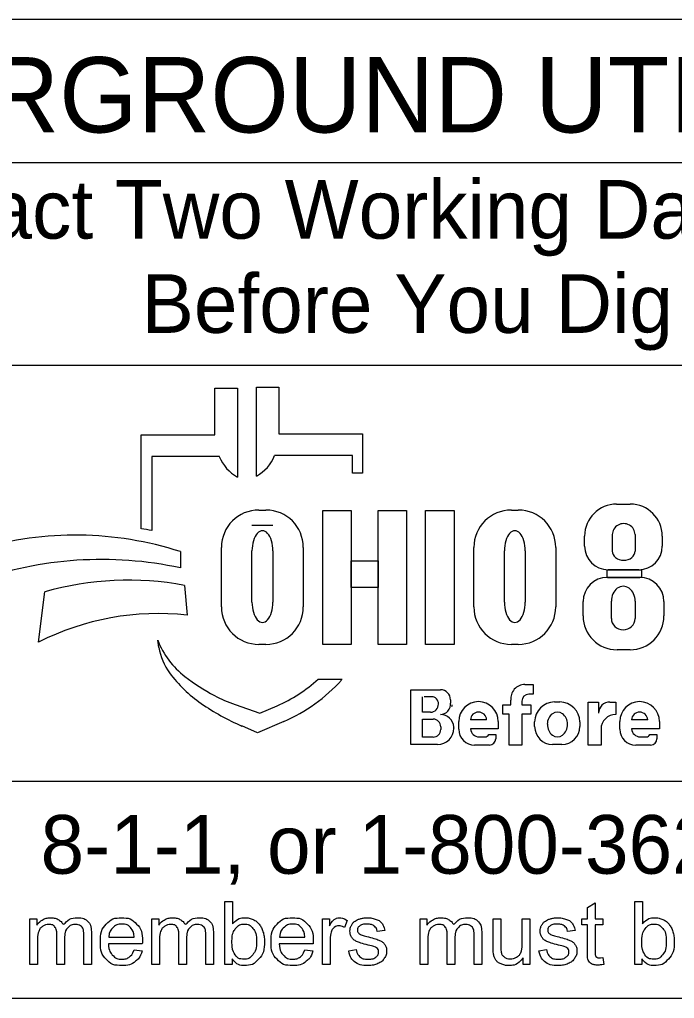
# Model space of a CAD drawing. Extents: x 25.6 to 80.6, y 0.2 to 24.5.
# Drawn here: x 38.78 to 40.344, y 2.373 to 4.711 of the extents above; entities that cross this region are included whole.
import ezdxf

# ---------------------------------------------------------------- set-up
doc = ezdxf.new("R2010")
doc.units = 0
doc.layers.add('SH_Data', color=7, linetype='Continuous')
doc.layers.add('SH_Text', color=7, linetype='Continuous')

msp = doc.modelspace()

# ---------------------------------------------------------------- linework, layer by layer
at = {"layer": 'SH_Data'}
for p, q in [((42.1403, 4.7105), (37.8903, 4.7105)), ((37.8903, 4.369), (42.1403, 4.369)), ((37.8903, 3.8856), (42.1403, 3.8856)), ((42.1403, 2.8909), (37.8903, 2.8909)), ((42.1403, 2.373), (37.8903, 2.373))]:
    msp.add_line(p, q, dxfattribs=at)
at = {"layer": 'SH_Text'}
for p, q in [((39.2463, 3.7186), (39.2463, 3.83)), ((39.2463, 3.83), (39.3, 3.83)), ((39.3, 3.83), (39.3, 3.618)), ((39.3457, 3.6203), (39.3457, 3.8324)), ((39.3457, 3.8324), (39.3993, 3.8324)), ((39.3993, 3.8324), (39.3993, 3.7209)), ((39.0704, 3.4947), (39.0704, 3.7186)), ((39.0704, 3.7186), (39.2463, 3.7186)), ((39.3993, 3.7209), (39.5985, 3.7209)), ((39.5985, 3.7209), (39.5985, 3.6271)), ((39.0956, 3.6671), (39.0956, 3.4903)), ((39.2568, 3.6671), (39.0956, 3.6671)), ((39.5753, 3.6694), (39.3889, 3.6694)), ((39.5753, 3.6271), (39.5753, 3.6694)), ((39.5985, 3.6271), (39.5753, 3.6271)), ((40.2059, 3.5534), (40.2386, 3.5534)), ((39.3513, 3.5394), (39.3679, 3.5394)), ((39.9544, 3.5394), (39.9709, 3.5394)), ((39.3846, 3.5024), (39.3348, 3.5024)), ((40.1296, 3.4528), (40.1296, 3.4771)), ((40.1958, 3.4414), (40.1958, 3.4807)), ((40.2499, 3.4807), (40.2499, 3.4414)), ((40.315, 3.4771), (40.315, 3.4528)), ((39.1637, 3.44), (39.1637, 3.4012)), ((39.2619, 3.3079), (39.2619, 3.4499)), ((39.3348, 3.3193), (39.3348, 3.4416)), ((39.3846, 3.4416), (39.3846, 3.3193)), ((39.4573, 3.4499), (39.4573, 3.3079)), ((39.8649, 3.3079), (39.8649, 3.4499)), ((39.9378, 3.3193), (39.9378, 3.4416)), ((39.9876, 3.4416), (39.9876, 3.3193)), ((40.0604, 3.4499), (40.0604, 3.3079)), ((40.259, 3.3968), (40.1856, 3.3968)), ((40.1838, 3.3785), (40.2611, 3.3785)), ((38.8248, 3.2238), (38.8395, 3.344)), ((39.1736, 3.3594), (39.1799, 3.2884)), ((40.1259, 3.2865), (40.1259, 3.3206)), ((40.1934, 3.2806), (40.1934, 3.3215)), ((40.2502, 3.3215), (40.2502, 3.2806)), ((40.319, 3.3206), (40.319, 3.2865)), ((39.1125, 3.2109), (39.1095, 3.2289)), ((39.3679, 3.2184), (39.3513, 3.2184)), ((39.9709, 3.2184), (39.9544, 3.2184)), ((40.238, 3.2056), (40.2069, 3.2056)), ((39.4928, 3.1351), (39.5503, 3.1351)), ((39.7141, 2.9793), (39.7141, 3.11)), ((39.7141, 3.11), (39.7853, 3.11)), ((39.9867, 3.1228), (40.0062, 3.1228)), ((40.0062, 3.1228), (40.0062, 3.0998)), ((39.7421, 3.0565), (39.7421, 3.0935)), ((39.7673, 3.0935), (39.746, 3.0935)), ((39.8091, 3.0863), (39.8091, 3.0784)), ((40.0062, 3.0994), (39.996, 3.0994)), ((39.2944, 3.0747), (39.3538, 3.0542)), ((39.3538, 3.0542), (39.3949, 3.072)), ((39.9341, 3.0515), (39.9341, 3.0744)), ((39.9341, 3.0744), (39.9534, 3.0744)), ((39.9534, 3.0744), (39.9534, 3.0849)), ((39.9795, 3.0829), (39.9795, 3.0744)), ((39.9795, 3.0744), (40.0011, 3.0744)), ((40.0011, 3.0744), (40.0011, 3.0515)), ((40.0579, 3.081), (40.0701, 3.081)), ((40.1382, 2.9781), (40.1382, 3.0808)), ((40.1382, 3.0808), (40.1627, 3.0808)), ((40.1627, 3.0808), (40.1627, 3.0539)), ((40.19, 3.0808), (40.2038, 3.0808)), ((40.2038, 3.0808), (40.2038, 3.0511)), ((39.7615, 3.0565), (39.7421, 3.0565)), ((39.7421, 2.9971), (39.7421, 3.04)), ((39.7421, 3.04), (39.7676, 3.04)), ((39.949, 3.0515), (39.9341, 3.0515)), ((39.949, 2.9781), (39.949, 3.0515)), ((40.0011, 3.0515), (39.9795, 3.0515)), ((39.9795, 3.0515), (39.9795, 2.9781)), ((39.3478, 3.0072), (39.3105, 3.0236)), ((39.4111, 3.0346), (39.3478, 3.0072)), ((39.7857, 3.0219), (39.7857, 3.0155)), ((39.8171, 3.019), (39.8171, 3.0186)), ((39.8287, 3.0161), (39.8287, 3.0345)), ((39.8952, 3.0385), (39.8567, 3.0385)), ((39.9232, 3.0168), (39.8568, 3.0168)), ((39.9232, 3.0345), (39.9232, 3.0168)), ((40.0101, 3.0224), (40.0101, 3.0332)), ((40.1179, 3.0332), (40.1179, 3.0224)), ((40.1687, 3.0162), (40.1687, 2.9781)), ((40.2136, 3.0161), (40.2136, 3.0345)), ((40.2802, 3.0385), (40.2416, 3.0385)), ((40.3081, 3.0168), (40.2417, 3.0168)), ((40.3081, 3.0345), (40.3081, 3.0168)), ((39.7674, 2.9971), (39.7421, 2.9971)), ((39.8777, 2.9976), (39.8918, 2.9976)), ((39.9004, 3.0031), (39.9173, 3.0031)), ((39.9173, 3.0031), (39.9173, 2.9933)), ((40.2626, 2.9976), (40.2767, 2.9976)), ((40.2853, 3.0031), (40.3022, 3.0031)), ((40.3022, 3.0031), (40.3022, 2.9933)), ((39.7778, 2.9793), (39.7141, 2.9793)), ((39.902, 2.9781), (39.8666, 2.9781)), ((39.9795, 2.9781), (39.949, 2.9781)), ((40.0751, 2.9796), (40.0529, 2.9796)), ((40.1687, 2.9781), (40.1382, 2.9781)), ((40.287, 2.9781), (40.2516, 2.9781))]:
    msp.add_line(p, q, dxfattribs=at)
for points in [[(39.5038, 3.5383), (39.5717, 3.5383), (39.5717, 3.2184), (39.5038, 3.2184)], [(39.6359, 3.5383), (39.7039, 3.5383), (39.7039, 3.2184), (39.6359, 3.2184)], [(39.7492, 3.5383), (39.818, 3.5383), (39.818, 3.2184), (39.7492, 3.2184)], [(39.5717, 3.4184), (39.6359, 3.4184), (39.6359, 3.3544), (39.5717, 3.3544)], [(40.1834, 3.3968), (40.2651, 3.3968), (40.2651, 3.3783), (40.1834, 3.3783)]]:
    msp.add_lwpolyline(points, close=True, dxfattribs=at)
for points in [[(39.2871, 2.4542), (39.2701, 2.4542), (39.2701, 2.6043), (39.2885, 2.6043), (39.2885, 2.5508)], [(40.1361, 2.486), (40.1361, 2.5487), (40.1225, 2.5487), (40.1225, 2.563), (40.1361, 2.563), (40.1361, 2.59), (40.1545, 2.601), (40.1545, 2.563), (40.1729, 2.563), (40.1729, 2.5487), (40.1545, 2.5487), (40.1545, 2.4849)], [(40.2662, 2.4542), (40.2491, 2.4542), (40.2491, 2.6043), (40.2676, 2.6043), (40.2676, 2.5508)], [(38.804, 2.4542), (38.804, 2.563), (38.8205, 2.563), (38.8205, 2.5477)], [(39.0954, 2.4542), (39.0954, 2.563), (39.1119, 2.563), (39.1119, 2.5477)], [(39.5032, 2.4542), (39.5032, 2.563), (39.5198, 2.563), (39.5198, 2.5465)], [(39.5623, 2.5595), (39.5558, 2.5425)], [(39.7364, 2.4542), (39.7364, 2.563), (39.7529, 2.563), (39.7529, 2.5477)], [(39.9107, 2.4956), (39.9107, 2.563), (39.9292, 2.563), (39.9292, 2.5027)], [(39.9804, 2.5047), (39.9804, 2.563), (39.9989, 2.563), (39.9989, 2.4542), (39.9824, 2.4542)], [(38.8871, 2.5173), (38.8871, 2.4542), (38.8687, 2.4542), (38.8687, 2.5248)], [(38.9516, 2.5288), (38.9516, 2.4542), (38.9331, 2.4542), (38.9331, 2.5227)], [(39.1785, 2.5173), (39.1785, 2.4542), (39.1601, 2.4542), (39.1601, 2.5248)], [(39.2429, 2.5288), (39.2429, 2.4542), (39.2245, 2.4542), (39.2245, 2.5227)], [(39.6522, 2.5349), (39.6341, 2.5325)], [(39.8195, 2.5173), (39.8195, 2.4542), (39.8011, 2.4542), (39.8011, 2.5248)], [(39.8839, 2.5288), (39.8839, 2.4542), (39.8655, 2.4542), (39.8655, 2.5227)], [(40.1068, 2.5349), (40.0887, 2.5325)], [(38.8225, 2.5106), (38.8225, 2.4542), (38.804, 2.4542)], [(39.0728, 2.5038), (38.9916, 2.5038)], [(38.9927, 2.519), (39.0534, 2.519)], [(39.1138, 2.5106), (39.1138, 2.4542), (39.0954, 2.4542)], [(39.4808, 2.5038), (39.3996, 2.5038)], [(39.4007, 2.519), (39.4614, 2.519)], [(39.5216, 2.5112), (39.5216, 2.4542), (39.5032, 2.4542)], [(39.7548, 2.5106), (39.7548, 2.4542), (39.7364, 2.4542)], [(39.0532, 2.4893), (39.0723, 2.4869)], [(39.4612, 2.4893), (39.4803, 2.4869)], [(39.5658, 2.4867), (39.584, 2.4895)], [(40.0204, 2.4867), (40.0386, 2.4895)], [(39.2871, 2.4678), (39.2871, 2.4542)], [(39.9824, 2.4542), (39.9824, 2.4702)], [(40.1729, 2.4706), (40.1756, 2.4543)], [(40.2662, 2.4678), (40.2662, 2.4542)]]:
    msp.add_lwpolyline(points, dxfattribs=at)
for centre, radius, start, end in [((39.3481, 3.7039), 0.0985, 201.9296, 240.7469), ((39.2975, 3.7062), 0.0985, 299.2531, 338.0704), ((40.2059, 3.4771), 0.0763, 90, 180), ((40.2386, 3.4771), 0.0763, 0, 90), ((39.3513, 3.4499), 0.0895, 90, 180), ((39.3679, 3.4499), 0.0895, 0, 90), ((39.9544, 3.4499), 0.0895, 90, 180), ((39.9709, 3.4499), 0.0895, 0, 90), ((38.9423, 2.6857), 0.8191, 79.2074, 81.0007), ((38.9125, 2.6604), 0.8191, 72.1402, 106.3144), ((40.1856, 3.4528), 0.056, 180, 270), ((40.259, 3.4528), 0.056, 270, 0), ((38.9756, 2.5293), 0.8919, 77.8238, 109.8274), ((39.0395, 2.6396), 0.7322, 79.44, 105.8467), ((40.1838, 3.3206), 0.0579, 90, 180), ((40.2611, 3.3206), 0.0579, 0, 90), ((39.3513, 3.3079), 0.0895, 180, 270), ((39.3679, 3.3079), 0.0895, 270, 0), ((39.9544, 3.3079), 0.0895, 180, 270), ((39.9709, 3.3079), 0.0895, 270, 0), ((39.1115, 2.6564), 0.6357, 83.8248, 116.8021), ((40.2069, 3.2865), 0.081, 180, 270), ((40.238, 3.2865), 0.081, 270, 0), ((39.2969, 3.301), 0.2008, 201.0457, 232.5314), ((39.2538, 3.235), 0.1433, 189.6817, 216.0884), ((39.3875, 3.3325), 0.3088, 216.0884, 235.7167), ((39.4894, 3.5522), 0.5173, 232.5314, 241.794), ((39.2515, 3.4025), 0.3602, 293.4582, 312.0712), ((39.2515, 3.4025), 0.401, 293.4582, 317.8286), ((39.7853, 3.0863), 0.0238, 0, 90), ((39.9867, 3.0893), 0.0335, 90, 187.5187), ((39.4042, 3.3934), 0.3371, 241.794, 250.9821), ((39.7634, 3.0766), 0.0169, 357.8325, 90), ((39.996, 3.0829), 0.0165, 90, 180), ((39.554, 3.5767), 0.6044, 235.7167, 246.2325), ((39.7615, 3.0753), 0.0187, 270, 2.0582), ((39.7849, 3.0755), 0.0243, 270, 6.6529), ((39.7955, 3.0741), 0.0175, 347.4023, 0), ((39.8759, 3.0345), 0.0473, 0, 180), ((40.0579, 3.0332), 0.0478, 90, 180), ((40.0701, 3.0332), 0.0478, 0, 90), ((40.1896, 3.0539), 0.0269, 89.2449, 180), ((40.2609, 3.0345), 0.0473, 0, 180), ((39.7676, 3.0219), 0.0181, 0, 90), ((39.785, 3.0191), 0.0321, 4.0748, 90), ((39.876, 3.0375), 0.0193, 2.9632, 177.0368), ((40.2036, 3.0162), 0.0349, 89.6033, 180), ((40.2609, 3.0375), 0.0193, 2.9632, 177.0368), ((39.7674, 3.0155), 0.0184, 270, 0), ((39.7778, 3.0186), 0.0393, 270, 0), ((39.7842, 3.019), 0.033, 0, 11.7502), ((39.8666, 3.0161), 0.038, 180, 270), ((39.8777, 3.0186), 0.021, 184.827, 270), ((40.0529, 3.0224), 0.0428, 180, 270), ((40.0751, 3.0224), 0.0428, 270, 0), ((40.2516, 3.0161), 0.038, 180, 270), ((40.2626, 3.0186), 0.021, 184.827, 270), ((39.8918, 3.007), 0.00938, 270, 335.9979), ((39.902, 2.9933), 0.0152, 270, 0), ((40.2767, 3.007), 0.00938, 270, 335.9979), ((40.287, 2.9933), 0.0152, 270, 0)]:
    msp.add_arc(centre, radius, start, end, dxfattribs=at)
for centre, major_axis, ratio, start_param, end_param in [((40.2228, 3.4807), (0.0271, 0), 0.969373, 0, 3.141593), ((39.3597, 3.4416), (0, 0.0484), 0.514403, 4.712389, 7.853982), ((39.9627, 3.4416), (0, 0.0484), 0.514403, 4.712389, 7.853982), ((40.2228, 3.4414), (0.0271, 0), 0.818453, 3.141593, 6.283185), ((40.2218, 3.3215), (0, 0.0358), 0.794529, 4.712389, 7.853982), ((39.3597, 3.3193), (0, 0.0484), 0.514403, 1.570796, 4.712389), ((39.9627, 3.3193), (0, 0.0484), 0.514403, 1.570796, 4.712389), ((40.2218, 3.2806), (0.0284, 0), 0.959837, 3.141593, 6.283185), ((40.0645, 3.0278), (0, 0.029), 0.832186, 4.712389, 7.853982), ((40.0645, 3.0278), (0, 0.0302), 0.797287, 1.570796, 4.712389)]:
    msp.add_ellipse(centre, major_axis=major_axis, ratio=ratio, start_param=start_param, end_param=end_param, dxfattribs=at)
for points in [[(38.8205, 2.5477), (38.8257, 2.5557), (38.8342, 2.5605), (38.8427, 2.5654), (38.8535, 2.5654), (38.8656, 2.5654), (38.8734, 2.5604), (38.8811, 2.5554), (38.8843, 2.5463), (38.8972, 2.5654), (38.9179, 2.5654), (38.9341, 2.5654), (38.9428, 2.5565), (38.9516, 2.5475), (38.9516, 2.5288)], [(38.8687, 2.5248), (38.8687, 2.5371), (38.8642, 2.5433), (38.8597, 2.5494), (38.8494, 2.5494), (38.8416, 2.5494), (38.835, 2.5453), (38.8284, 2.5412), (38.8254, 2.5333), (38.8225, 2.5254), (38.8225, 2.5106)], [(38.9331, 2.5227), (38.9331, 2.5337), (38.9313, 2.5386), (38.9296, 2.5435), (38.9248, 2.5464), (38.9201, 2.5494), (38.9138, 2.5494), (38.9023, 2.5494), (38.8947, 2.5418), (38.8871, 2.5341), (38.8871, 2.5173)], [(39.0723, 2.4869), (39.0678, 2.4702), (39.0556, 2.461), (39.0434, 2.4518), (39.0245, 2.4518), (39.0006, 2.4518), (38.9866, 2.4665), (38.9726, 2.4812), (38.9726, 2.5077), (38.9726, 2.5351), (38.9868, 2.5503), (39.0009, 2.5654), (39.0234, 2.5654), (39.0452, 2.5654), (39.0591, 2.5506), (39.0729, 2.5357), (39.0729, 2.5088), (39.0729, 2.5071), (39.0728, 2.5038)], [(39.0534, 2.519), (39.0522, 2.5327), (39.0465, 2.5396), (39.0377, 2.5503), (39.0236, 2.5503), (39.0109, 2.5503), (39.0023, 2.5418), (38.9936, 2.5332), (38.9927, 2.519)], [(39.1119, 2.5477), (39.117, 2.5557), (39.1255, 2.5605), (39.134, 2.5654), (39.1449, 2.5654), (39.157, 2.5654), (39.1647, 2.5604), (39.1725, 2.5554), (39.1756, 2.5463), (39.1886, 2.5654), (39.2093, 2.5654), (39.2255, 2.5654), (39.2342, 2.5565), (39.2429, 2.5475), (39.2429, 2.5288)], [(39.1601, 2.5248), (39.1601, 2.5371), (39.1556, 2.5433), (39.1511, 2.5494), (39.1408, 2.5494), (39.133, 2.5494), (39.1264, 2.5453), (39.1198, 2.5412), (39.1168, 2.5333), (39.1138, 2.5254), (39.1138, 2.5106)], [(39.2245, 2.5227), (39.2245, 2.5337), (39.2227, 2.5386), (39.2209, 2.5435), (39.2162, 2.5464), (39.2115, 2.5494), (39.2051, 2.5494), (39.1937, 2.5494), (39.1861, 2.5418), (39.1785, 2.5341), (39.1785, 2.5173)], [(39.2869, 2.5094), (39.2869, 2.4898), (39.2922, 2.4811), (39.3009, 2.4669), (39.3157, 2.4669), (39.3278, 2.4669), (39.3366, 2.4774), (39.3454, 2.4879), (39.3454, 2.5087), (39.3454, 2.53), (39.337, 2.5402), (39.3285, 2.5503), (39.3166, 2.5503), (39.3045, 2.5503), (39.2957, 2.5398), (39.2869, 2.5293), (39.2869, 2.5094)], [(39.2885, 2.5508), (39.3002, 2.5654), (39.3183, 2.5654), (39.3283, 2.5654), (39.3373, 2.5614), (39.3463, 2.5573), (39.352, 2.55), (39.3578, 2.5427), (39.3611, 2.5323), (39.3644, 2.522), (39.3644, 2.5102), (39.3644, 2.4823), (39.3506, 2.467), (39.3367, 2.4518), (39.3174, 2.4518), (39.2981, 2.4518), (39.2871, 2.4678)], [(39.4803, 2.4869), (39.4758, 2.4702), (39.4636, 2.461), (39.4514, 2.4518), (39.4325, 2.4518), (39.4086, 2.4518), (39.3946, 2.4665), (39.3806, 2.4812), (39.3806, 2.5077), (39.3806, 2.5351), (39.3948, 2.5503), (39.4089, 2.5654), (39.4314, 2.5654), (39.4532, 2.5654), (39.4671, 2.5506), (39.4809, 2.5357), (39.4809, 2.5088), (39.4809, 2.5071), (39.4808, 2.5038)], [(39.4614, 2.519), (39.4602, 2.5327), (39.4545, 2.5396), (39.4456, 2.5503), (39.4316, 2.5503), (39.4189, 2.5503), (39.4102, 2.5418), (39.4016, 2.5332), (39.4007, 2.519)], [(39.5198, 2.5465), (39.5261, 2.5581), (39.5315, 2.5617), (39.5369, 2.5654), (39.5433, 2.5654), (39.5526, 2.5654), (39.5623, 2.5595)], [(39.6341, 2.5325), (39.6329, 2.5409), (39.627, 2.5456), (39.6211, 2.5503), (39.6103, 2.5503), (39.5976, 2.5503), (39.5922, 2.5461), (39.5867, 2.5419), (39.5867, 2.5363), (39.5867, 2.5327), (39.589, 2.5298), (39.5913, 2.5268), (39.5961, 2.5249), (39.5988, 2.5238), (39.6124, 2.5201), (39.632, 2.5149), (39.6397, 2.5116), (39.6475, 2.5083), (39.6519, 2.5019), (39.6563, 2.4956), (39.6563, 2.4862), (39.6563, 2.477), (39.6509, 2.4688), (39.6456, 2.4607), (39.6354, 2.4562), (39.6252, 2.4518), (39.6124, 2.4518), (39.5912, 2.4518), (39.58, 2.4606), (39.5689, 2.4694), (39.5658, 2.4867)], [(39.584, 2.4895), (39.5855, 2.4786), (39.5926, 2.4727), (39.5996, 2.4669), (39.6123, 2.4669), (39.625, 2.4669), (39.6312, 2.4721), (39.6373, 2.4772), (39.6373, 2.4842), (39.6373, 2.4905), (39.6319, 2.4941), (39.6281, 2.4965), (39.613, 2.5003), (39.5927, 2.5054), (39.5848, 2.5092), (39.577, 2.5129), (39.5729, 2.5195), (39.5689, 2.5261), (39.5689, 2.5341), (39.5689, 2.5414), (39.5722, 2.5476), (39.5756, 2.5537), (39.5813, 2.5578), (39.5856, 2.561), (39.5931, 2.5632), (39.6005, 2.5654), (39.609, 2.5654), (39.6218, 2.5654), (39.6315, 2.5617), (39.6412, 2.558), (39.6458, 2.5517), (39.6505, 2.5454), (39.6522, 2.5349)], [(39.7529, 2.5477), (39.758, 2.5557), (39.7665, 2.5605), (39.775, 2.5654), (39.7859, 2.5654), (39.798, 2.5654), (39.8057, 2.5604), (39.8135, 2.5554), (39.8166, 2.5463), (39.8296, 2.5654), (39.8503, 2.5654), (39.8665, 2.5654), (39.8752, 2.5565), (39.8839, 2.5475), (39.8839, 2.5288)], [(39.8011, 2.5248), (39.8011, 2.5371), (39.7966, 2.5433), (39.7921, 2.5494), (39.7818, 2.5494), (39.774, 2.5494), (39.7674, 2.5453), (39.7608, 2.5412), (39.7578, 2.5333), (39.7548, 2.5254), (39.7548, 2.5106)], [(39.8655, 2.5227), (39.8655, 2.5337), (39.8637, 2.5386), (39.8619, 2.5435), (39.8572, 2.5464), (39.8525, 2.5494), (39.8461, 2.5494), (39.8347, 2.5494), (39.8271, 2.5418), (39.8195, 2.5341), (39.8195, 2.5173)], [(40.0887, 2.5325), (40.0875, 2.5409), (40.0816, 2.5456), (40.0757, 2.5503), (40.0649, 2.5503), (40.0522, 2.5503), (40.0468, 2.5461), (40.0413, 2.5419), (40.0413, 2.5363), (40.0413, 2.5327), (40.0436, 2.5298), (40.0458, 2.5268), (40.0507, 2.5249), (40.0534, 2.5238), (40.067, 2.5201), (40.0865, 2.5149), (40.0943, 2.5116), (40.1021, 2.5083), (40.1065, 2.5019), (40.1109, 2.4956), (40.1109, 2.4862), (40.1109, 2.477), (40.1055, 2.4688), (40.1001, 2.4607), (40.09, 2.4562), (40.0798, 2.4518), (40.067, 2.4518), (40.0457, 2.4518), (40.0346, 2.4606), (40.0235, 2.4694), (40.0204, 2.4867)], [(40.0386, 2.4895), (40.0401, 2.4786), (40.0472, 2.4727), (40.0542, 2.4669), (40.0668, 2.4669), (40.0796, 2.4669), (40.0857, 2.4721), (40.0919, 2.4772), (40.0919, 2.4842), (40.0919, 2.4905), (40.0865, 2.4941), (40.0826, 2.4965), (40.0676, 2.5003), (40.0473, 2.5054), (40.0394, 2.5092), (40.0316, 2.5129), (40.0275, 2.5195), (40.0235, 2.5261), (40.0235, 2.5341), (40.0235, 2.5414), (40.0268, 2.5476), (40.0301, 2.5537), (40.0359, 2.5578), (40.0402, 2.561), (40.0476, 2.5632), (40.0551, 2.5654), (40.0636, 2.5654), (40.0764, 2.5654), (40.0861, 2.5617), (40.0958, 2.558), (40.1004, 2.5517), (40.105, 2.5454), (40.1068, 2.5349)], [(40.266, 2.5094), (40.266, 2.4898), (40.2713, 2.4811), (40.28, 2.4669), (40.2948, 2.4669), (40.3069, 2.4669), (40.3157, 2.4774), (40.3245, 2.4879), (40.3245, 2.5087), (40.3245, 2.53), (40.316, 2.5402), (40.3076, 2.5503), (40.2956, 2.5503), (40.2836, 2.5503), (40.2748, 2.5398), (40.266, 2.5293), (40.266, 2.5094)], [(40.2676, 2.5508), (40.2792, 2.5654), (40.2974, 2.5654), (40.3074, 2.5654), (40.3164, 2.5614), (40.3253, 2.5573), (40.3311, 2.55), (40.3369, 2.5427), (40.3402, 2.5323), (40.3434, 2.522), (40.3434, 2.5102), (40.3434, 2.4823), (40.3296, 2.467), (40.3158, 2.4518), (40.2964, 2.4518), (40.2772, 2.4518), (40.2662, 2.4678)], [(39.5558, 2.5425), (39.5491, 2.5464), (39.5423, 2.5464), (39.5363, 2.5464), (39.5315, 2.5428), (39.5267, 2.5391), (39.5247, 2.5327), (39.5216, 2.5228), (39.5216, 2.5112)], [(38.9916, 2.5038), (38.9927, 2.4859), (39.0018, 2.4764), (39.0109, 2.4669), (39.0245, 2.4669), (39.0347, 2.4669), (39.0419, 2.4722), (39.049, 2.4776), (39.0532, 2.4893)], [(39.3996, 2.5038), (39.4007, 2.4859), (39.4098, 2.4764), (39.4189, 2.4669), (39.4325, 2.4669), (39.4427, 2.4669), (39.4499, 2.4722), (39.457, 2.4776), (39.4612, 2.4893)], [(39.9292, 2.5027), (39.9292, 2.4883), (39.9303, 2.4832), (39.932, 2.476), (39.9377, 2.4718), (39.9433, 2.4677), (39.9516, 2.4677), (39.9599, 2.4677), (39.9671, 2.4719), (39.9744, 2.4762), (39.9774, 2.4835), (39.9804, 2.4908), (39.9804, 2.5047)], [(39.9824, 2.4702), (39.9697, 2.4518), (39.9479, 2.4518), (39.9383, 2.4518), (39.9299, 2.4555), (39.9216, 2.4591), (39.9175, 2.4647), (39.9135, 2.4703), (39.9119, 2.4784), (39.9107, 2.4838), (39.9107, 2.4956)], [(40.1756, 2.4543), (40.1678, 2.4527), (40.1617, 2.4527), (40.1516, 2.4527), (40.1461, 2.4559), (40.1406, 2.4591), (40.1383, 2.4642), (40.1361, 2.4694), (40.1361, 2.486)], [(40.1545, 2.4849), (40.1545, 2.477), (40.1555, 2.4748), (40.1564, 2.4725), (40.1586, 2.4712), (40.1608, 2.4699), (40.1649, 2.4699), (40.1679, 2.4699), (40.1729, 2.4706)]]:
    msp.add_open_spline(points, degree=3, dxfattribs=at)

# ---------------------------------------------------------------- texts
for s, height, p in [('UNDERGROUND UTILITIES', 0.18, (38.0185, 4.4409)), ('Contact Two Working Days', 0.14, (38.31, 4.1874)), ('Before You Dig', 0.14, (39.0711, 3.9624)), ('OHIO811, 8-1-1, or 1-800-362-2764', 0.14, (37.9348, 2.6709))]:
    msp.add_text(s, height=height, dxfattribs=at).set_placement(p)

doc.saveas('drawing.dxf')
